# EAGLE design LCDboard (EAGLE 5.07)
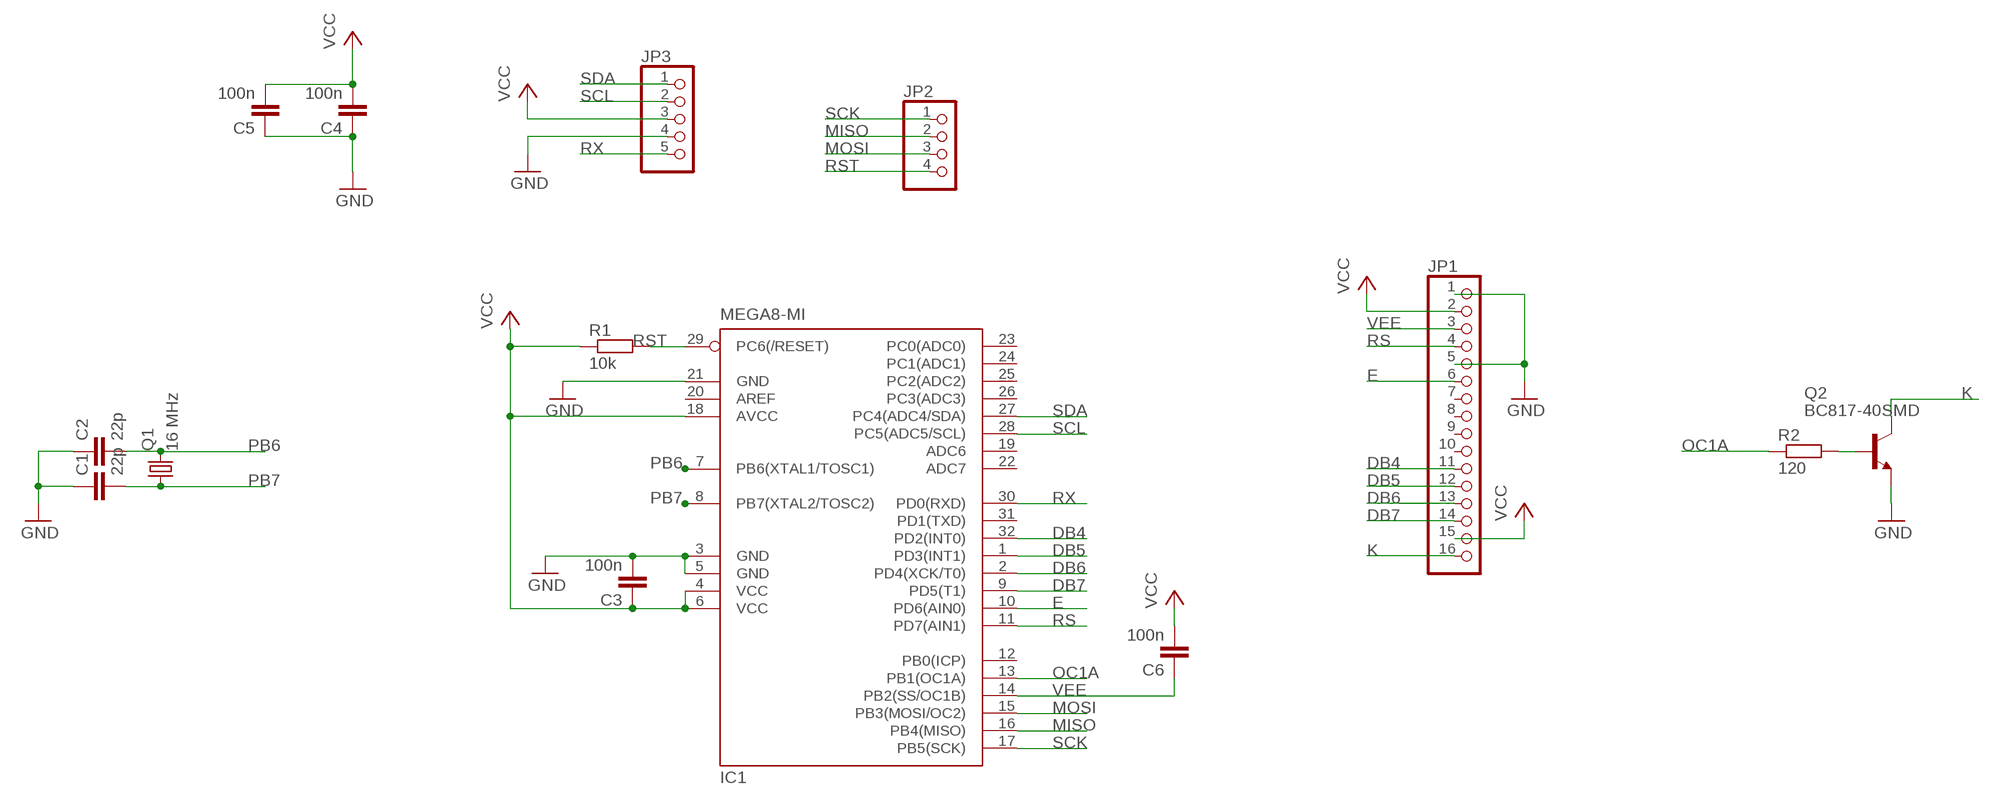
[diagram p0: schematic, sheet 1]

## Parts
C1  22p  C-EUC0805  [C0805]
C2  22p  C-EUC0805  [C0805]
C3  100n  C-EUC0805  [C0805]
C4  100n  C-EUC0805  [C0805]
C5  100n  C-EUC0805  [C0805]
C6  100n  C-EUC0805  [C0805]
IC1  MEGA8-MI  [MLF32]
JP1  PINHD-1X16  [1X16]
JP2  PINHD-1X4_2.54-SMD-90°  [1X04SMD/90]
JP3  PINHD-1X5/90  [1X05/90]
Q1  16 MHz  CRYSTAL5X3  [CRYSTAL-SMD-5X3]
Q2  BC817-40SMD  [SOT23-BEC]
R1  10k  R-EU_R0805  [R0805]
R2  120  R-EU_R0805  [R0805]

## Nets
DB4: IC1.32(PD2(INT0)) JP1.11
DB5: IC1.1(PD3(INT1)) JP1.12
DB6: IC1.2(PD4(XCK/T0)) JP1.13
DB7: IC1.9(PD5(T1)) JP1.14
E: IC1.10(PD6(AIN0)) JP1.6
GND: C1.1 C2.1 C3.2 C4.1 C5.1 IC1.3(GND) IC1.5(GND) IC1.21(GND) JP1.1 JP1.5 JP3.4 Q2.E
K: JP1.16 Q2.C
MISO: IC1.16(PB4(MISO)) JP2.2
MOSI: IC1.15(PB3(MOSI/OC2)) JP2.3
N$1: Q2.B R2.2
OC1A: IC1.13(PB1(OC1A)) R2.1
PB6: C2.2 IC1.7(PB6(XTAL1/TOSC1)) Q1.3
PB7: C1.2 IC1.8(PB7(XTAL2/TOSC2)) Q1.1
RS: IC1.11(PD7(AIN1)) JP1.4
RST: IC1.29(PC6(/RESET)) JP2.4 R1.2
RX: IC1.30(PD0(RXD)) JP3.5
SCK: IC1.17(PB5(SCK)) JP2.1
SCL: IC1.28(PC5(ADC5/SCL)) JP3.2
SDA: IC1.27(PC4(ADC4/SDA)) JP3.1
VCC: C3.1 C4.2 C5.2 C6.2 IC1.4(VCC) IC1.6(VCC) IC1.18(AVCC) JP1.2 JP1.15 JP3.3 R1.1
VEE: C6.1 IC1.14(PB2(SS/OC1B)) JP1.3
Unconnected: IC1.12(PB0(ICP)) IC1.19(ADC6) IC1.20(AREF) IC1.22(ADC7) IC1.23(PC0(ADC0)) IC1.24(PC1(ADC1)) IC1.25(PC2(ADC2)) IC1.26(PC3(ADC3)) IC1.31(PD1(TXD)) JP1.7 JP1.8 JP1.9 JP1.10

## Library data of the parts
C1-C6 = rcl:C-EU: CAPACITOR, European symbol
IC1 = atmel:MEGA8: MICROCONTROLLER 8 Kbytes FLASH, 1 kbytes SRAM, 512 bytes EEPROM, USART, 6-channel 10 bit ADC, 2-channel 8 bit ADC Pin compatible with Atmega48, ATMega88, ATMega168 Source: avr.lbr
JP1 = pinhead:PINHD-1X16: PIN HEADER
JP2 = pinhead2:PINHD-1X4: PIN HEADER
JP3 = pinhead:PINHD-1X5: PIN HEADER
Q1 = SparkFun:CRYSTAL: Crystals
Q2 = transistor-npn:BC817*: NPN Transistor
R1 R2 = rcl:R-EU_: RESISTOR, European symbol

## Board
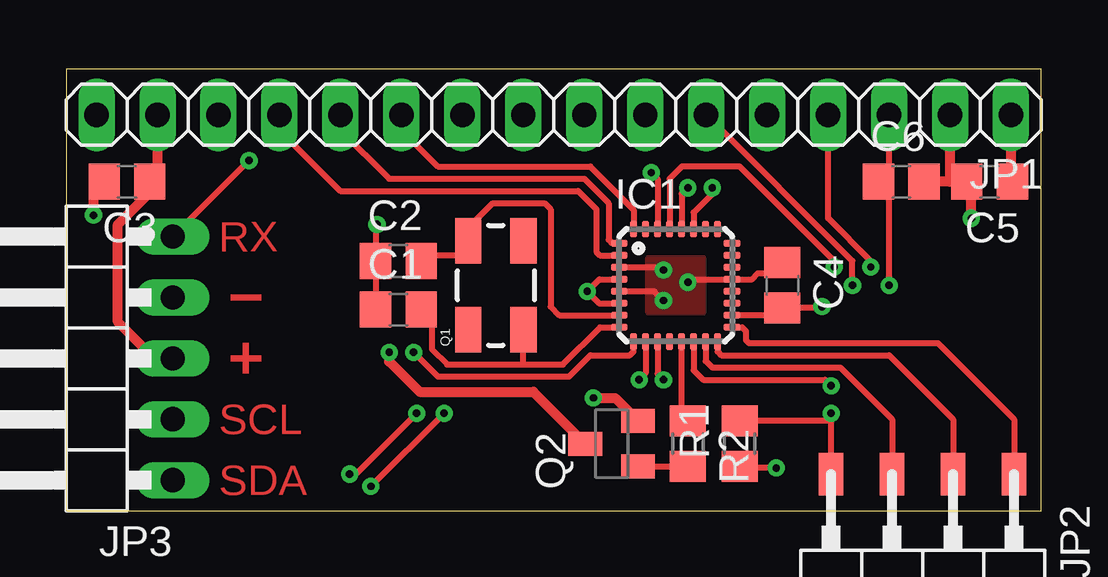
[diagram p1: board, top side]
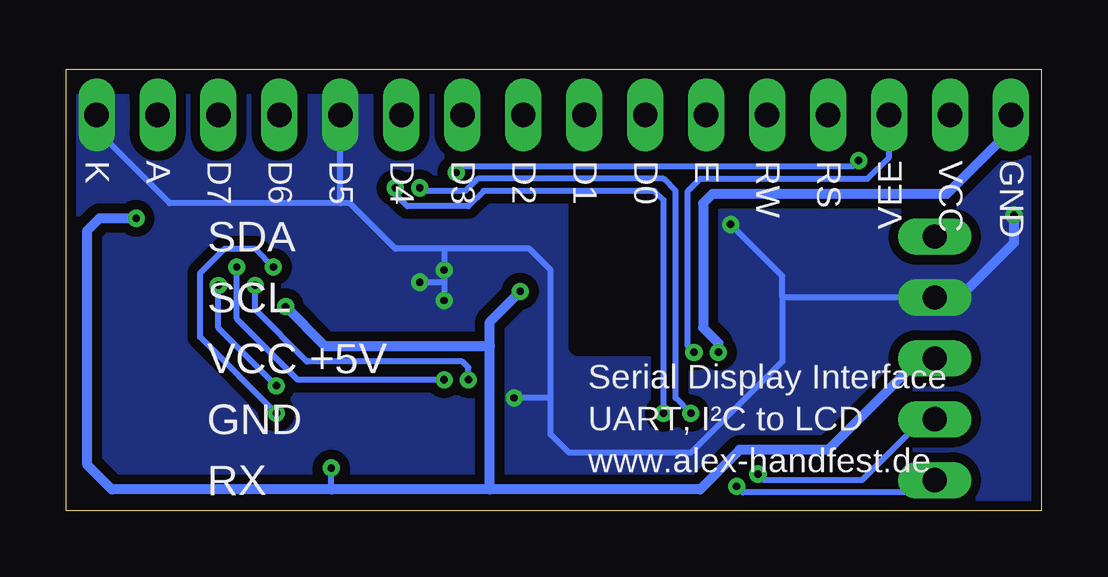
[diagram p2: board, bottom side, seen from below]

Size 40.64 x 18.41 mm. Coordinates in mm from the lower left corner, seen from the top.
Outline: 0,0 40.63,0 40.64,18.41 0,18.41 0,0
Copper layers (1*16): Top 0.035mm / dielectric 1.5mm / Bottom 0.035mm
Design rules "default *": minimum track width 10mil, minimum drill 12mil, track to track 8mil, track to pad 7mil, pad to pad 7mil, via to via 7mil, smd to smd 7mil, copper to edge 15mil, drill to drill 8mil, minimum pad ring 10mil, minimum via ring 8mil, stop-mask expansion 4mil, vias tented up to drill 12mil, thermal gap 10mil
bRestrict: area 16.1,6.9 to 19.3,13

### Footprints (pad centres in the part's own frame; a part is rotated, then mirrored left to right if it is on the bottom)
C0805 = smd 1.3 x 1.5: 1 -0.95,0; 2 0.95,0
MLF32 = smd 0.7 x 0.3: 1 -2.35,1.75; 2 -2.35,1.25; 3 -2.35,0.75; 4 -2.35,0.25; 5 -2.35,-0.25; 6 -2.35,-0.75; 7 -2.35,-1.25; 8 -2.35,-1.75; 17 2.35,-1.75; 18 2.35,-1.25; 19 2.35,-0.75; 20 2.35,-0.25; 21 2.35,0.25; 22 2.35,0.75; 23 2.35,1.25; 24 2.35,1.75 | smd 0.3 x 0.7: 9 -1.75,-2.35; 10 -1.25,-2.35; 11 -0.75,-2.35; 12 -0.25,-2.35; 13 0.25,-2.35; 14 0.75,-2.35; 15 1.25,-2.35; 16 1.75,-2.35; 25 1.75,2.35; 26 1.25,2.35; 27 0.75,2.35; 28 0.25,2.35; 29 -0.25,2.35; 30 -0.75,2.35; 31 -1.25,2.35; 32 -1.75,2.35
1X16 = drill 1.016 long: 1 -19.05,0; 2 -16.51,0; 3 -13.97,0; 4 -11.43,0; 5 -8.89,0; 6 -6.35,0; 7 -3.81,0; 8 -1.27,0; 9 1.27,0; 10 3.81,0; 11 6.35,0; 12 8.89,0; 13 11.43,0; 14 13.97,0; 15 16.51,0; 16 19.05,0
1X04SMD/90 = smd 1.016 x 1.778: 1 -1.27,-5.08; 2 1.27,-5.08; 3 3.81,-5.08; 4 6.35,-5.08
1X05/90 = drill 1.016 long: 1 -5.08,-3.81; 2 -2.54,-3.81; 3 0,-3.81; 4 2.54,-3.81; 5 5.08,-3.81
CRYSTAL-SMD-5X3 = smd 1.9 x 1.1: 1 -1.85,-1.15; 2 1.85,-1.15; 3 1.85,1.15; 4 -1.85,1.15
SOT23-BEC = smd 1 x 1.4: B -0.95,-1.1; C 0,1.1; E 0.95,-1.1
R0805 = smd 1.3 x 1.5: 1 -0.95,0; 2 0.95,0

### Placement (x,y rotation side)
C1  13.84,8.38 0 top
C2  13.84,10.41 0 top
C3  2.54,13.72 180 top
C4  29.84,9.4 270 top
C5  38.48,13.72 180 top
C6  34.8,13.72 0 top
IC1  25.4,9.4 0 top
JP1  20.32,16.51 180 top
JP2  38.23,-3.56 180 top
JP3  0.64,6.35 90 top
Q1  17.91,9.4 90 top
Q2  22.73,2.79 90 top
R1  28.07,2.79 90 top
R2  25.91,2.79 270 top

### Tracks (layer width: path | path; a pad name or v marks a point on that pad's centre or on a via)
DB4
  Top 0.254: IC1.32 23.65,12.54 21.84,14.35 15.49,14.35 13.97,15.88 JP1.11
DB5
  Top 0.254: JP1.12 11.43,15.88 13.46,13.84 21.59,13.84 22.61,12.83 22.61,11.3 22.76,11.15 IC1.1
DB6
  Top 0.254: IC1.2 22.25,10.65 22.1,10.79 22.1,12.57 21.34,13.34 11.43,13.34 8.89,15.88 JP1.13
DB7  (via drill 0.3)
  Top 0.254: IC1.9 23.65,6.63 23.5,6.48 21.84,6.48 20.95,5.59 15.49,5.59 v14.48,6.6
  Bottom 0.254: v14.48,6.6 14.73,6.86 14.73,13.34 14.22,13.84 7.24,13.84 6.35,14.73 JP1.14
E  (via drill 0.3)
  Top 0.254: IC1.10 24.15,5.74 v23.88,5.46 | v32.77,9.4 32.77,10.41 JP1.6
  Bottom 0.254: v23.88,5.46 23.88,5.97 24.13,6.22 30.61,6.22 32.77,8.38 v32.77,9.4
GND  (via drill 0.3)
  Top 0.254: C4.1 29.4,9.91 28.83,9.91 28.57,9.65 IC1.21 26.03,9.65 v25.91,9.53 | v12.95,11.94 12.89,11.88 C2.1 C1.1 | IC1.5 24.51,9.15 v24.89,8.76 | IC1.3 24.78,10.15 v24.89,10.03
  Top 0.406: JP1.1 39.37,13.78 C5.1 | Q2.E 22.88,4.7 v21.97,4.7 | C3.2 1.59,13.65 1.14,13.21 v1.14,12.32
  Bottom 0.254: JP3.4 10.79,8.89 | JP1.1 39.37,15.88 36.32,12.83 29.21,12.83 | 29.21,12.83 28.83,12.83 26.92,10.92 24.89,10.92 | 29.21,12.83 JP1.5 | 24.89,10.92 21.34,10.92 20.45,10.03 20.45,4.7 | v12.95,11.94 10.79,9.78 10.79,8.89 | 10.79,8.89 10.79,6.22 14.61,2.41 19.68,2.41 20.45,3.17 20.45,4.7 | 20.45,4.7 v21.97,4.7 | 24.89,10.92 v24.89,10.03 24.89,9.53 | 24.89,9.53 v24.89,8.76 | 24.89,9.53 v25.91,9.53
  Bottom 0.406: v1.14,12.32 1.14,11.18 3.43,8.89 JP3.4
  pour Bottom (isolate 0.406, no thermals): -0.32,17.24 40.96,17.24 40.96,-0.32 -0.32,-0.32
  pour Top: 24.26,10.54 26.54,10.54 26.54,8.26 24.26,8.26
K  (via drill 0.3)
  Top 0.406: Q2.C 19.47,4.95 14.73,4.95 13.46,6.22 v13.46,6.6
  Bottom 0.406: JP1.16 1.27,15.88 3.94,13.21 13.72,13.21 14.1,12.83 14.1,7.62 13.46,6.99 v13.46,6.6
MISO
  Top 0.254: IC1.16 27.15,6.63 27.3,6.48 34.29,6.48 36.96,3.81 JP2.2
MOSI
  Top 0.254: IC1.15 26.65,6.24 26.92,5.97 32.26,5.97 34.42,3.81 JP2.3
N$1
  Top 0.254: Q2.B R2.2
OC1A
  Top 0.254: IC1.13 25.65,4 R2.1
PB6
  Top 0.254: IC1.7 20.55,8.15 20.19,8.51 20.19,12.57 19.94,12.83 17.78,12.83 16.76,11.8 Q1.3 16.76,10.91 16.51,10.67 15.05,10.67 C2.2
PB7
  Top 0.254: 19.06,6.1 20.7,6.1 22.25,7.65 IC1.8 | 19.06,6.1 Q1.1 | 19.06,6.1 15.88,6.1 15.24,6.73 15.24,7.93 C1.2
RS  (via drill 0.3)
  Top 0.254: IC1.11 24.65,5.7 v24.89,5.46 | v33.53,10.16 33.53,10.41 31.75,12.19 JP1.4
  Bottom 0.254: v24.89,5.46 30.99,5.46 33.53,8 v33.53,10.16
RST  (via drill 0.3)
  Top 0.254: IC1.29 25.15,13.85 25.65,14.35 28.07,14.35 32,10.41 v32,10.16 | JP2.4 v31.88,4.06 31.88,3.74 R1.2
  Bottom 0.254: v32,10.16 32.77,10.92 34.04,10.92 35.05,9.91 35.05,7.24 v31.88,4.06
RX  (via drill 0.3)
  Top 0.254: IC1.30 24.65,13.83 v24.38,14.1 | JP3.5 v7.62,14.61
  Bottom 0.254: v24.38,14.1 24.13,14.35 7.87,14.35 v7.62,14.61
SCK
  Top 0.254: IC1.17 28.17,7.65 28.32,7.49 28.32,7.11 28.45,6.99 36.32,6.99 39.5,3.81 JP2.1
SCL  (via drill 0.3)
  Top 0.254: IC1.28 25.65,13.2 v25.91,13.46 | v11.81,1.52 12.06,1.52 v14.61,4.06
  Bottom 0.254: v25.91,13.46 25.78,13.34 24,13.34 23.5,13.84 15.75,13.84 15.24,13.34 15.24,4.7 v14.61,4.06 | v11.81,1.52 11.56,1.27 7.49,1.27 4.95,3.81 JP3.2
SDA  (via drill 0.3)
  Top 0.254: IC1.27 26.15,12.43 26.92,13.21 v26.92,13.46 | v12.7,1.02 v15.75,4.06
  Bottom 0.254: v26.92,13.46 26.92,13.21 26.42,12.7 23.88,12.7 23.24,13.34 16.13,13.34 15.75,12.95 v15.75,4.06 | JP3.1 4.95,0.76 12.45,0.76 v12.7,1.02
VCC  (via drill 0.3)
  Top 0.254: v31.5,8.51 31.43,8.45 C4.2 29.55,8.15 IC1.18 | v29.59,1.78 28.13,1.78 R1.1 | IC1.6 22.21,8.65 v21.72,9.14 22.22,9.65 IC1.4
  Top 0.406: 36.83,13.72 JP1.2 | 36.83,13.72 C6.2 | 36.83,13.72 C5.2 37.72,13.53 v37.72,12.19 | JP3.3 3.68,6.35 2.16,7.87 2.16,11.94 3.49,13.27 C3.1 3.81,14.04 JP1.15
  Bottom 0.254: 29.59,0.89 v29.59,1.78
  Bottom 0.406: v31.5,8.51 29.84,6.86 22.99,6.86 | JP3.3 5.08,6.35 8.89,2.54 12.57,2.54 14.22,0.89 22.99,0.89 | 22.99,0.89 22.99,6.86 | 22.99,6.86 22.99,7.87 v21.72,9.14 | 22.99,0.89 29.59,0.89 38.73,0.89 39.75,1.91 39.75,11.68 39.24,12.19 v37.72,12.19
VEE  (via drill 0.3)
  Top 0.254: JP1.3 34.29,14.16 C6.1 34.29,13.27 v34.29,9.4 | IC1.14 26.15,5.85 26.54,5.46 31.62,5.46 v31.88,5.21
  Bottom 0.254: v31.88,5.21 34.29,7.62 v34.29,9.4
(copper drawn outside any net)
  shapes: Top area x3

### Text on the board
Top: RX | SCL | SDA
bNames: GND | VCC | VEE | RS | RW | E | D0 | D1 | D2 | D3 | D4 | D5 | D6 | D7 | A | K | SDA | SCL | VCC +5V | Serial Display Interface | UART, I²C to LCD | GND | www.alex-handfest.de | RX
